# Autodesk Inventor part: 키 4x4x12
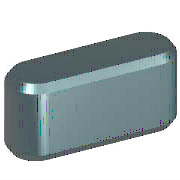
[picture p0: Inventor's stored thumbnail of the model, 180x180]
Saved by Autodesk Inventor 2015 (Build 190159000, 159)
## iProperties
IsCustomPart: 1
Created: 2012-02
Part Number: 키 4x4x12
Material: 강철, 연강
Description: 키 및 해당 키홈
Document SubType Name: Modeling
Standard: KS B 1311
Designer: mduedu
Standards Organization: KS
Language: ko-KR
Size Designation: 4 x 4 x 12
Categories: <MemberInstance><Categories><Category DisplayName="샤프트 부품" InternalName="7f7aeb1f-a693-4053-b835-cee3144e0d98" Mnemonic="SHFT"><Category DisplayName="키" Interna
Density: 1 g/cm^3
Appearance: 노란색
Author: mduedu
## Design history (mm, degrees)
workplane "Work Plane1"
workplane "Work Plane2"
sketch "스케치1"
  geometry: L1 (2, 2)-(10, 2); L2 (10, -2)-(2, -2); L3 (0, 9.4)-(0, -7.4) reference; L4 (-5, 0)-(30, 0) reference; L5 (12, 0)-(12, 7); A1 r 2 centre (2, 0) between (2, 2) and (2, -2); A2 r 2 centre (10, 0) between (10, -2) and (10, 2)
  constraints: 6 end point, 5 point on circle, 4 tangent, 3 point on line, 2 centre point, 1 horizontal, 1 parallel, 1 perpendicular
  dimensions: "d0" = 2 radius of A1 (= 0.5 x PB); "d13" = 2 radius of A2 (= 0.5 x PB); "d14" = 12 distance between parallel lines of L5 L3 (= NLG)
extrude "본체1" new body sketch "스케치1" taper "d3" = 0 deg; stored distance "d4" = 10
workplane "Work Plane3"
body "Solid1"
chamfer "모따기1" distance "d8" = 0.25 (= PHH); stored, may be unused: second distance "d9" = 0.25 (= PHH), angle "d15" = 45 deg
other parameters: "d1" = -2.5 (= -PNT), "d2" = 1.5 (= PH - PNT), "NLG" = 12 [user parameter; used in 3 equation terms], "PB" = 4 [user parameter; used in 2 equation terms], "PNT" = 2.5 [user parameter; used in 2 equation terms], "PH" = 4 [user parameter; used in 1 equation term], "PHH" = 0.25 [user parameter; used in 2 equation terms], "d10" = 0, "d16" = 0, "d17" = 0, "d18" = 0, "PLB2" = 12 (= NLG) [user parameter], "WDMAX" = 12 [user parameter], "PLB1" = 12 (= NLG) [user parameter], "RR" = 0.08 [user parameter], "PUEB" = 1.8 [user parameter]
